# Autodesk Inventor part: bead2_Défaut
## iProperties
Shininess: 64.0
Length Units: 11269
Angle Units: 11279
Time Units: 11290
Mass Units: 11283
Length Display Precision: 3
Angle Display Precision: 2
Compacted: True
Part Number: bead2_Défaut
Document SubType Name: Modeling
Created: 2006-11
Material: Par défaut
Designer: profs_sti
Density: 0.0
Volumn: 0.0
Area: 0.0
PropertySet Name: Model Information
Control State: 0
Master: False
Checked Out: False
Author: profs_sti
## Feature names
1. Base1
